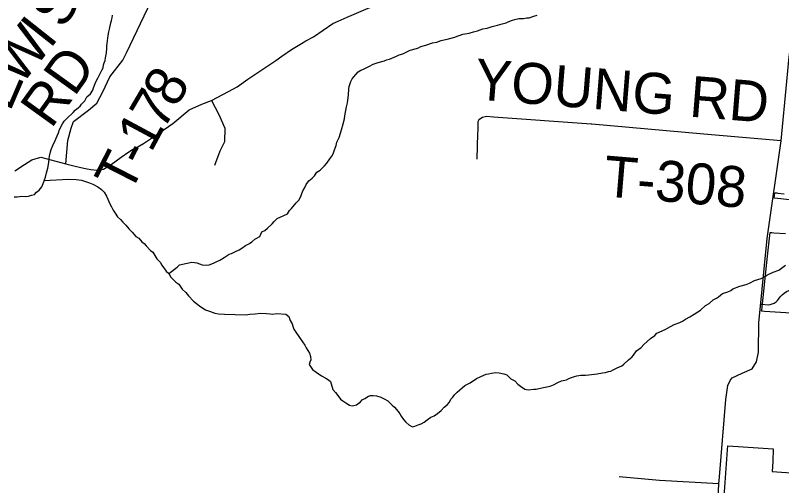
# Model space of a CAD drawing. Extents: x 0 to 39.3, y -3.9 to 22.
# Drawn here: x 2.753 to 3.818, y 17.092 to 17.745 of the extents above; entities that cross this region are included whole.
import ezdxf

# ---------------------------------------------------------------- set-up
doc = ezdxf.new("R2010")
doc.units = 0
for name, color, linetype in [('GM_X_Corporation', 7, 'Continuous'), ('GM_X_Minor_River', 7, 'Continuous'), ('GM_X_Township_Road', 7, 'Continuous'), ('GM_X_Township_Road_Text', 7, 'Continuous')]:
    doc.layers.add(name, color=color, linetype=linetype)

msp = doc.modelspace()

# ---------------------------------------------------------------- linework, layer by layer
at = {"layer": 'GM_X_Corporation'}
for points in [[(3.8284, 17.4889), (3.8166, 17.4902), (3.8074, 17.4913), (3.8082, 17.4988), (3.811, 17.4985), (3.8126, 17.4983), (3.8212, 17.4974)], [(3.8313, 17.3313), (3.7941, 17.3338), (3.79, 17.334), (3.7901, 17.3358), (3.7982, 17.4104), (3.8005, 17.4313), (3.8018, 17.4434), (3.8044, 17.4433), (3.8071, 17.4431), (3.8071, 17.4431), (3.823, 17.442)], [(3.7377, 17.0703), (3.7427, 17.1415), (3.743, 17.147), (3.7643, 17.1457), (3.8061, 17.1431), (3.8054, 17.1254), (3.8047, 17.1114), (3.8641, 17.1071)]]:
    msp.add_lwpolyline(points, dxfattribs=at)
at = {"layer": 'GM_X_Minor_River'}
for points in [[(2.8866, 17.7381), (2.8875, 17.7419), (2.8879, 17.7453)], [(3.4348, 17.735), (3.4379, 17.7364), (3.4436, 17.7386), (3.4471, 17.7397), (3.4528, 17.7407), (3.4558, 17.741), (3.4589, 17.741), (3.4638, 17.7417), (3.4672, 17.742), (3.4737, 17.7442), (3.4779, 17.7456)], [(2.7513, 17.4932), (2.7555, 17.4931), (2.762, 17.4938), (2.7666, 17.4937), (2.7711, 17.494), (2.7753, 17.4954), (2.7795, 17.4965), (2.7826, 17.4995), (2.7861, 17.5025), (2.79, 17.507), (2.7924, 17.5138), (2.7936, 17.5168), (2.7948, 17.5206), (2.7964, 17.5266), (2.798, 17.5331), (2.7993, 17.5407), (2.8001, 17.546), (2.8006, 17.5498), (2.8018, 17.5554), (2.8026, 17.5589), (2.805, 17.5645), (2.8082, 17.5713), (2.8109, 17.5777), (2.8129, 17.5819), (2.8145, 17.5868), (2.8184, 17.5943), (2.8208, 17.5981), (2.8247, 17.6018), (2.8332, 17.6104), (2.8363, 17.6134), (2.8432, 17.619), (2.8451, 17.622), (2.8494, 17.6265), (2.8525, 17.6318), (2.8572, 17.6363), (2.8607, 17.6415), (2.8615, 17.6446), (2.8639, 17.6506), (2.8651, 17.654), (2.8674, 17.6581), (2.8702, 17.6634), (2.8733, 17.6691), (2.8749, 17.6725), (2.8757, 17.6763), (2.8765, 17.6793), (2.8777, 17.6823), (2.8782, 17.6861), (2.8798, 17.6933), (2.8803, 17.6994), (2.8803, 17.7028), (2.8808, 17.7062), (2.8821, 17.7172), (2.8829, 17.7222), (2.8838, 17.726), (2.8858, 17.7347), (2.8866, 17.7381)], [(2.9662, 17.3863), (2.9778, 17.3953), (2.9809, 17.3986), (2.9916, 17.4011), (2.9981, 17.4021), (3.0019, 17.4017), (3.0053, 17.4012), (3.0087, 17.4), (3.0128, 17.3988), (3.0193, 17.3983), (3.0223, 17.3987), (3.0285, 17.4008), (3.0319, 17.4027), (3.0373, 17.4052), (3.043, 17.4089), (3.0503, 17.4134), (3.0534, 17.4141), (3.0588, 17.417), (3.0641, 17.4192), (3.0676, 17.4215), (3.0726, 17.4255), (3.0783, 17.4281), (3.0818, 17.4303), (3.0857, 17.4341), (3.0926, 17.4381), (3.0957, 17.4442), (3.0996, 17.4464), (3.1034, 17.4497), (3.11, 17.4557), (3.1127, 17.4587), (3.117, 17.4628), (3.1311, 17.4694), (3.1339, 17.4739), (3.1366, 17.4769), (3.1432, 17.4848), (3.1474, 17.4889), (3.1502, 17.4949), (3.1526, 17.5014), (3.1549, 17.5051), (3.1569, 17.51), (3.1608, 17.5153), (3.1654, 17.519), (3.1685, 17.5224), (3.172, 17.5273), (3.1766, 17.5299), (3.1828, 17.5362), (3.1859, 17.54), (3.1898, 17.546), (3.1929, 17.5494), (3.1945, 17.5528), (3.1965, 17.5584), (3.1989, 17.5645), (3.1997, 17.569), (3.2029, 17.5754), (3.2061, 17.586), (3.2085, 17.5944), (3.2102, 17.6016), (3.211, 17.6057), (3.2131, 17.6182), (3.2147, 17.6235), (3.2151, 17.6273), (3.216, 17.6345), (3.2162, 17.6433), (3.217, 17.6463), (3.219, 17.6531), (3.221, 17.6569), (3.2233, 17.6599), (3.2295, 17.6666), (3.233, 17.6689), (3.2368, 17.6703), (3.2452, 17.6747), (3.2502, 17.6773), (3.2571, 17.6795), (3.2659, 17.682), (3.2689, 17.6835), (3.2731, 17.6845), (3.2827, 17.6885), (3.2865, 17.6904), (3.2915, 17.6918), (3.3015, 17.697), (3.3103, 17.6991), (3.3133, 17.7002), (3.3164, 17.702), (3.3233, 17.7038), (3.3328, 17.7071), (3.3389, 17.7081), (3.3447, 17.7103), (3.355, 17.7124), (3.3638, 17.7149), (3.3668, 17.7164), (3.371, 17.7178), (3.3748, 17.7189), (3.3836, 17.7206), (3.3897, 17.7224), (3.3951, 17.7239), (3.4027, 17.7264), (3.4084, 17.7274), (3.4157, 17.7296), (3.423, 17.7314), (3.4295, 17.7335), (3.4348, 17.735)], [(2.7931, 17.5157), (2.8267, 17.5177), (2.8373, 17.5172), (2.8449, 17.5163), (2.8479, 17.5155), (2.8562, 17.5126), (2.8608, 17.5107), (2.8675, 17.5071), (2.8728, 17.5032), (2.8762, 17.4994), (2.8795, 17.494), (2.8817, 17.4898), (2.8842, 17.4832), (2.8868, 17.479), (2.8887, 17.4744), (2.8916, 17.4702), (2.895, 17.4652), (2.8991, 17.4617), (2.9024, 17.4578), (2.9066, 17.4536), (2.9107, 17.4485), (2.9151, 17.4439), (2.9204, 17.4381), (2.9245, 17.4354), (2.9286, 17.4307), (2.932, 17.428), (2.9346, 17.4249), (2.9406, 17.4183), (2.9439, 17.416), (2.9495, 17.4068), (2.954, 17.4021), (2.9566, 17.3979), (2.9625, 17.3898), (2.9662, 17.3863), (2.9692, 17.3813), (2.9759, 17.3744), (2.9801, 17.3716), (2.9849, 17.3647), (2.9898, 17.36), (2.9935, 17.3554), (3.0006, 17.3481), (3.0047, 17.3449), (3.0107, 17.3403), (3.0171, 17.336), (3.0228, 17.334), (3.0303, 17.3316), (3.0353, 17.3307), (3.0436, 17.3298), (3.0733, 17.3293), (3.079, 17.33), (3.0862, 17.3306), (3.0942, 17.3312), (3.1022, 17.3311), (3.1071, 17.3306), (3.1105, 17.3302), (3.1162, 17.3308), (3.1288, 17.3298), (3.1329, 17.3267), (3.1347, 17.3214), (3.1377, 17.3168), (3.1384, 17.3133), (3.1398, 17.3091), (3.1428, 17.3049), (3.1469, 17.2991), (3.1487, 17.296), (3.1554, 17.2868), (3.1573, 17.2833), (3.1617, 17.2756), (3.1631, 17.271), (3.1634, 17.2665), (3.1623, 17.2634), (3.1611, 17.26), (3.1659, 17.2531), (3.1708, 17.2496), (3.1783, 17.2445), (3.1843, 17.241), (3.1881, 17.239), (3.1911, 17.2363), (3.1918, 17.2333), (3.1943, 17.2252), (3.1977, 17.221), (3.2025, 17.2152), (3.2047, 17.2121), (3.2081, 17.2094), (3.2122, 17.207), (3.2175, 17.2035), (3.2213, 17.2027), (3.227, 17.2041), (3.2324, 17.2082), (3.2351, 17.2112), (3.2386, 17.213), (3.2436, 17.216), (3.2466, 17.2171), (3.2501, 17.217), (3.255, 17.2166), (3.2607, 17.2146), (3.2656, 17.2122), (3.2705, 17.2094), (3.2735, 17.2067), (3.2768, 17.2036), (3.2798, 17.2009)], [(3.7896, 17.3795), (3.7942, 17.3821), (3.7973, 17.384), (3.8061, 17.3884), (3.8138, 17.3913), (3.8176, 17.3939), (3.823, 17.3983)], [(3.2798, 17.2009), (3.285, 17.1947), (3.2873, 17.1913), (3.2891, 17.1882), (3.2925, 17.1836), (3.2958, 17.1801), (3.2999, 17.1762), (3.3048, 17.1735), (3.3083, 17.1742), (3.3129, 17.1764), (3.3167, 17.1778), (3.3209, 17.18), (3.3251, 17.1834), (3.3305, 17.1867), (3.3351, 17.1889), (3.3397, 17.1922), (3.3448, 17.1963), (3.349, 17.2008), (3.3529, 17.2042), (3.3563, 17.2076), (3.3583, 17.2117), (3.3607, 17.2147), (3.3634, 17.2177), (3.3669, 17.2218), (3.3777, 17.2311), (3.3849, 17.2344), (3.3938, 17.2404), (3.3991, 17.2429), (3.4041, 17.2451), (3.4072, 17.2466), (3.4106, 17.2469), (3.4148, 17.248), (3.4209, 17.249), (3.4251, 17.2486), (3.4319, 17.2469), (3.4361, 17.2457), (3.4417, 17.2403), (3.447, 17.2375), (3.4511, 17.2329), (3.4548, 17.2298), (3.4608, 17.2259), (3.4654, 17.225), (3.4734, 17.2257), (3.4768, 17.226), (3.4806, 17.2267), (3.4871, 17.2281), (3.4963, 17.2302), (3.5008, 17.2317), (3.507, 17.2353), (3.512, 17.2372), (3.5188, 17.2389), (3.5223, 17.2404), (3.5257, 17.2422), (3.5299, 17.2433), (3.533, 17.2444), (3.5387, 17.2451), (3.5421, 17.2454), (3.5452, 17.2453), (3.5501, 17.2456), (3.5615, 17.2469), (3.5688, 17.2483), (3.573, 17.249), (3.5772, 17.2505), (3.5806, 17.2508), (3.5837, 17.2526), (3.5894, 17.2556), (3.5956, 17.2581), (3.5987, 17.2604), (3.6048, 17.2667), (3.6095, 17.2701), (3.6122, 17.2731), (3.6161, 17.2791), (3.6226, 17.2835), (3.6265, 17.288), (3.6354, 17.2963), (3.6415, 17.3003), (3.6442, 17.3037), (3.6561, 17.3088), (3.6592, 17.3107), (3.6684, 17.3155), (3.6764, 17.3184), (3.6799, 17.3202), (3.6841, 17.3232), (3.6902, 17.3261), (3.6964, 17.3298), (3.7014, 17.3331), (3.7052, 17.3357), (3.7118, 17.3421), (3.7172, 17.3447), (3.7226, 17.3499), (3.7272, 17.3521), (3.7303, 17.3543), (3.7357, 17.3588), (3.7429, 17.3609), (3.7471, 17.3631), (3.7502, 17.365), (3.7598, 17.369), (3.7686, 17.3711), (3.7732, 17.3733), (3.7801, 17.377), (3.7896, 17.3795)]]:
    msp.add_lwpolyline(points, dxfattribs=at)
at = {"layer": 'GM_X_Township_Road'}
for points in [[(2.9073, 17.6931), (3.0401, 17.9711), (3.0491, 18.0452), (3.0522, 18.0679), (3.0526, 18.0775), (3.0543, 18.0871), (3.0578, 18.0964), (3.0611, 18.1025), (3.0658, 18.1084), (3.0714, 18.1149), (3.0785, 18.1264), (3.0873, 18.1409), (3.0955, 18.1531)], [(3.2014, 17.7371), (3.2139, 17.7427), (3.2431, 17.7553), (3.2766, 17.7658), (3.4151, 17.8153), (3.4463, 17.8256), (3.4676, 17.8319), (3.4866, 17.8388), (3.4969, 17.8448), (3.513, 17.8577), (3.5507, 17.8977), (3.5621, 17.9056), (3.5709, 17.9124), (3.5759, 17.9153), (3.5835, 17.9164), (3.6032, 17.9165), (3.6816, 17.9191), (3.6823, 17.9191), (3.8533, 17.9236)], [(3.7869, 17.3273), (3.7978, 17.4351), (3.8172, 17.571), (3.8252, 17.6531), (3.828, 17.6829), (3.8356, 17.7483), (3.8386, 17.7814), (3.8523, 17.9138)], [(2.7524, 17.529), (2.7658, 17.5381), (2.776, 17.5447), (2.7886, 17.5482), (2.8231, 17.5391), (2.8361, 17.5358), (2.844, 17.5337), (2.8505, 17.5325), (2.8579, 17.531), (2.8669, 17.5301), (2.8757, 17.5315), (2.8862, 17.5379), (2.9, 17.548), (2.9107, 17.5554), (2.9157, 17.5589), (2.9224, 17.562), (2.9309, 17.5674), (2.9464, 17.5775), (2.972, 17.5951), (2.9944, 17.6141), (3.0119, 17.6218), (3.0254, 17.627), (3.0491, 17.6393), (3.0614, 17.6457), (3.0761, 17.6565), (3.115, 17.6827), (3.1234, 17.6887), (3.1368, 17.6976), (3.1505, 17.7062), (3.1566, 17.7099), (3.1673, 17.7154), (3.1943, 17.7338), (3.2014, 17.7371)], [(2.8231, 17.5391), (2.8259, 17.5714), (2.8307, 17.5884), (2.8339, 17.5976), (2.8546, 17.6134), (2.8664, 17.6234), (2.8747, 17.6388), (2.8843, 17.6596), (2.9024, 17.6828), (2.9073, 17.6931)], [(3.0254, 17.627), (3.0359, 17.6074), (3.0439, 17.5883), (3.0436, 17.5693), (3.0371, 17.5564), (3.0297, 17.5367)], [(3.554, 17.5941), (3.553, 17.5942), (3.4174, 17.6036), (3.4079, 17.6045), (3.4021, 17.6034), (3.3969, 17.6001), (3.3958, 17.5972), (3.3958, 17.5937), (3.3955, 17.5858)], [(3.8172, 17.571), (3.7097, 17.5802), (3.554, 17.5941)], [(3.3955, 17.5858), (3.3953, 17.5809), (3.3943, 17.5452)], [(3.7886, 17.3438), (3.7902, 17.3437), (3.799, 17.343), (3.802, 17.3434), (3.8049, 17.3442), (3.8076, 17.3455), (3.81, 17.3472), (3.8119, 17.3489), (3.8135, 17.3509), (3.8159, 17.3541), (3.8185, 17.3568), (3.8214, 17.3592), (3.8245, 17.3613), (3.8278, 17.363), (3.8313, 17.3644), (3.8349, 17.3654), (3.8385, 17.3661), (3.8423, 17.3663), (3.846, 17.3662), (3.8694, 17.3649), (3.9375, 17.3603), (4.0055, 17.3557), (4.0716, 17.3512)], [(3.7316, 17.1041), (3.7404, 17.2113), (3.7431, 17.2308), (3.7465, 17.2379), (3.749, 17.2414), (3.7632, 17.2481), (3.7769, 17.2541), (3.7829, 17.2638), (3.7856, 17.2774), (3.786, 17.3185), (3.7869, 17.3273)], [(3.7307, 17.0943), (3.6479, 17.099), (3.5922, 17.104)], [(3.7292, 17.0647), (3.7307, 17.0943), (3.7316, 17.1041)]]:
    msp.add_lwpolyline(points, dxfattribs=at)

# ---------------------------------------------------------------- texts
at = {"layer": 'GM_X_Township_Road_Text'}
for s, height, rotation, p in [('S', 0.0568, 61.8302, (2.8216, 17.7249)), ('I', 0.0568, 51.6218, (2.801, 17.6974)), ('W', 0.0568, 51.7018, (2.7602, 17.6458)), ('RD', 0.05682, 54.2383, (2.8027, 17.5864)), ('YOUNG RD', 0.05682, 355.396, (3.3897, 17.6287)), ('E', 0.0568, 66.7142, (2.7454, 17.6101)), ('8', 0.0568, 60.8696, (2.9764, 17.615)), ('7', 0.0568, 59.5244, (2.9579, 17.5835)), ('1', 0.0568, 61.7521, (2.9416, 17.5532)), ('-', 0.0568, 62.6704, (2.931, 17.5327)), ('T', 0.0568, 62.95, (2.9118, 17.4949)), ('T-308', 0.05682, 355.2368, (3.569, 17.4939))]:
    msp.add_text(s, height=height, rotation=rotation, dxfattribs=at).set_placement(p)

doc.saveas('drawing.dxf')
